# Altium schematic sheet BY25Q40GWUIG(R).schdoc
size 127 x 101 mm
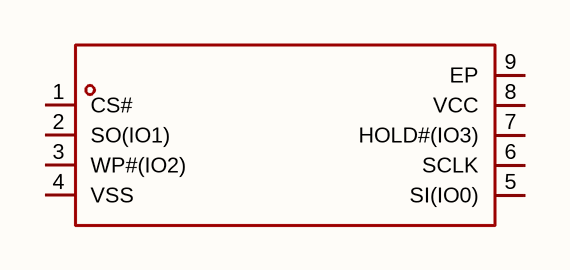
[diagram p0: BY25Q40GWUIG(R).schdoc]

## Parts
U?  by25q40gwuig(r)  [USON-8_L3.0-W2.0-P0.50-BL-EP_P25XX]  (value not drawn)

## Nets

Not connected (* = marked no-connect by the designer): U? 1(CS#) 2(SO(IO1)) 3(WP#(IO2)) 4(VSS) 5(SI(IO0)) 6(SCLK) 7(HOLD#(IO3)) 8(VCC) 9(EP)

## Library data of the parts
U? = by25q40gwuig(r): Manufacturer: BOYAMICRO(博雅); AddInBom: yes; ModelId: 12a239e5c7384371915ecb51201bf581; ModelName: USON-8_L3.0-W2.0-H0.6-P0.50; ModelTransform: 118.8974,78.74,0,90,0,0,0,0,0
